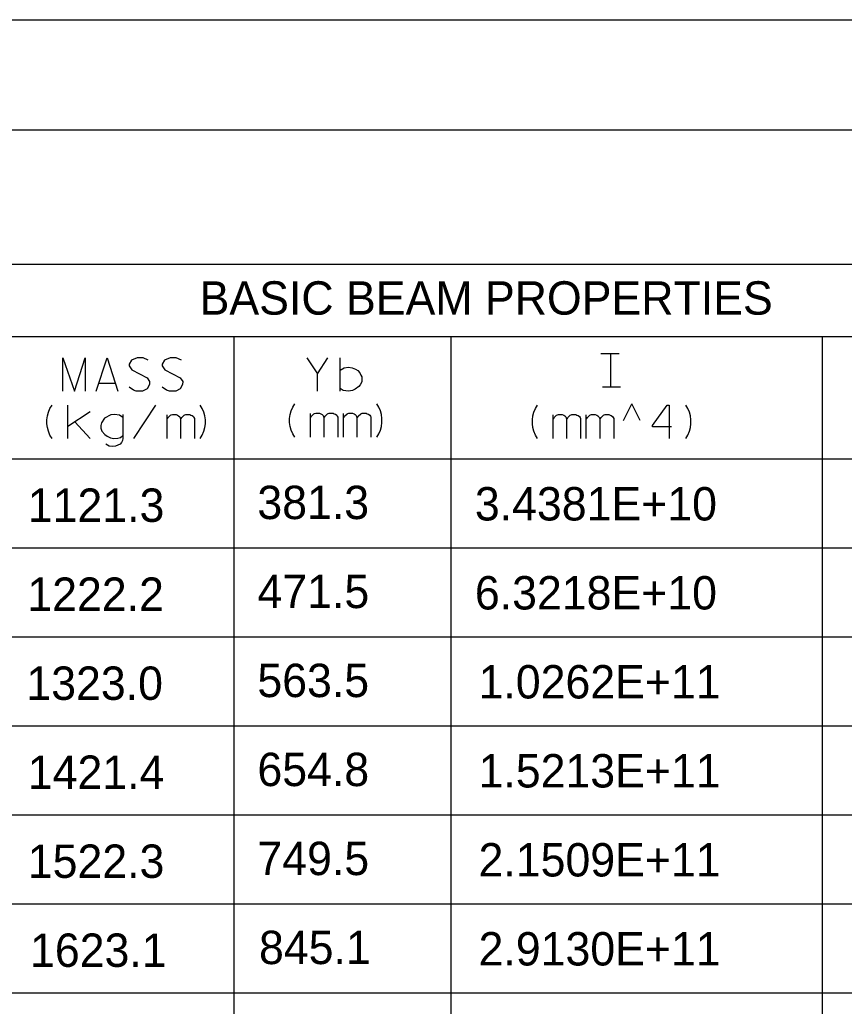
# Model space of a CAD drawing. Extents: x 635698 to 639877, y 296617 to 300175.
# Drawn here: x 637124.1 to 637198.2, y 298773.1 to 298861.8 of the extents above; entities that cross this region are included whole.
import ezdxf

# ---------------------------------------------------------------- set-up
doc = ezdxf.new("R2010")
doc.units = 0
doc.layers.add('2', color=7, linetype='Continuous')

msp = doc.modelspace()

# ---------------------------------------------------------------- linework, layer by layer
at = {"layer": '2'}
for p, q in [((636545.451, 298861.762), (637331.451, 298861.762)), ((637262.964, 298851.842), (636554.201, 298851.842)), ((637262.964, 298839.752), (636768.839, 298839.752)), ((637262.964, 298833.252), (637078.964, 298833.252)), ((637143.339, 298833.252), (637143.339, 298750.252)), ((637162.839, 298833.252), (637162.839, 298750.252)), ((637196.214, 298833.252), (637196.214, 298750.252)), ((637176.339, 298831.752), (637177.964, 298831.752)), ((637176.464, 298828.752), (637178.089, 298828.752)), ((637178.37, 298825.737), (637179.12, 298827.237)), ((637179.87, 298825.737), (637179.12, 298827.237)), ((637262.964, 298822.252), (636768.839, 298822.252)), ((637262.964, 298822.252), (637078.964, 298822.252)), ((637262.964, 298814.252), (636768.839, 298814.252)), ((637262.964, 298806.252), (636768.839, 298806.252)), ((637262.964, 298798.252), (636768.839, 298798.252)), ((637262.964, 298790.252), (636768.839, 298790.252)), ((637262.964, 298782.252), (636768.839, 298782.252)), ((637262.964, 298774.252), (636768.839, 298774.252))]:
    msp.add_line(p, q, dxfattribs=at)
for points in [[(637127.992, 298828.381), (637127.992, 298831.381), (637129.032, 298828.381), (637130, 298831.381), (637130, 298828.381)], [(637130.969, 298828.381), (637131.961, 298831.381), (637132.929, 298828.381)], [(637135.67, 298831.169), (637135.197, 298831.381), (637134.654, 298831.381), (637134.158, 298831.169), (637133.945, 298830.791), (637133.945, 298830.649), (637134.182, 298830.295), (637135.552, 298829.586), (637135.788, 298829.255), (637135.764, 298828.972), (637135.552, 298828.594), (637135.15, 298828.381), (637134.583, 298828.381), (637134.323, 298828.476), (637133.945, 298828.735)], [(637138.646, 298831.169), (637138.174, 298831.381), (637137.631, 298831.381), (637137.135, 298831.169), (637136.922, 298830.791), (637136.922, 298830.649), (637137.158, 298830.295), (637138.528, 298829.586), (637138.765, 298829.255), (637138.741, 298828.972), (637138.528, 298828.594), (637138.127, 298828.381), (637137.56, 298828.381), (637137.3, 298828.476), (637136.922, 298828.735)], [(637149.921, 298831.381), (637150.866, 298829.94), (637151.81, 298831.381)], [(637152.897, 298828.381), (637152.897, 298831.381)], [(637176.875, 298831.752), (637177.584, 298831.752)], [(637177.23, 298828.752), (637177.23, 298831.752)], [(637152.897, 298830.271), (637153.275, 298830.484), (637153.653, 298830.531), (637153.984, 298830.484), (637154.291, 298830.342), (637154.48, 298830.224), (637154.669, 298830.011), (637154.763, 298829.822), (637154.858, 298829.657), (637154.858, 298829.208), (637154.716, 298828.948), (637154.598, 298828.806), (637154.244, 298828.546), (637154.008, 298828.429), (637153.653, 298828.381), (637153.181, 298828.429), (637152.897, 298828.618)], [(637150.866, 298828.381), (637150.866, 298829.94)], [(637131.205, 298829.09), (637132.693, 298829.09)], [(637176.875, 298828.752), (637177.584, 298828.752)], [(637127.023, 298824.128), (637126.834, 298824.435), (637126.693, 298824.765), (637126.598, 298825.096), (637126.551, 298825.45), (637126.551, 298825.805), (637126.598, 298826.159), (637126.693, 298826.49), (637126.834, 298826.82), (637127.023, 298827.128)], [(637128.426, 298824.128), (637128.426, 298827.128)], [(637134.379, 298824.128), (637136.339, 298827.128)], [(637140.332, 298824.128), (637140.521, 298824.435), (637140.663, 298824.765), (637140.757, 298825.096), (637140.805, 298825.45), (637140.805, 298825.805), (637140.757, 298826.159), (637140.663, 298826.49), (637140.521, 298826.82), (637140.332, 298827.128)], [(637148.834, 298824.245), (637148.645, 298824.552), (637148.504, 298824.883), (637148.409, 298825.213), (637148.362, 298825.568), (637148.362, 298825.922), (637148.409, 298826.277), (637148.504, 298826.607), (637148.645, 298826.938), (637148.834, 298827.245)], [(637156.19, 298824.245), (637156.379, 298824.552), (637156.521, 298824.883), (637156.615, 298825.213), (637156.662, 298825.568), (637156.662, 298825.922), (637156.615, 298826.277), (637156.521, 298826.607), (637156.379, 298826.938), (637156.19, 298827.245)], [(637170.645, 298824.128), (637170.456, 298824.435), (637170.315, 298824.765), (637170.22, 298825.096), (637170.173, 298825.45), (637170.173, 298825.805), (637170.22, 298826.159), (637170.315, 298826.49), (637170.456, 298826.82), (637170.645, 298827.128)], [(637182.678, 298825.167), (637180.978, 298825.167), (637180.978, 298825.285), (637182.3, 298827.128), (637182.466, 298827.128), (637182.466, 298824.128)], [(637183.954, 298824.128), (637184.143, 298824.435), (637184.285, 298824.765), (637184.379, 298825.096), (637184.427, 298825.45), (637184.427, 298825.805), (637184.379, 298826.159), (637184.285, 298826.49), (637184.143, 298826.82), (637183.954, 298827.128)], [(637130.458, 298826.513), (637128.426, 298825.214)], [(637133.387, 298826.017), (637133.08, 298826.23), (637132.631, 298826.277), (637132.3, 298826.254), (637131.733, 298825.946), (637131.45, 298825.521), (637131.403, 298825.285), (637131.403, 298825.049), (637131.497, 298824.765), (637131.757, 298824.482), (637131.969, 298824.316), (637132.276, 298824.175), (637132.56, 298824.128), (637132.938, 298824.151), (637133.174, 298824.222), (637133.387, 298824.387)], [(637133.387, 298826.277), (637133.387, 298824.128), (637133.34, 298823.939), (637133.268, 298823.773), (637133.127, 298823.608), (637132.938, 298823.513), (637132.725, 298823.443), (637132.465, 298823.395), (637132.158, 298823.443), (637131.852, 298823.608)], [(637137.356, 298825.875), (637137.403, 298825.923), (637137.45, 298826.017), (637137.663, 298826.23), (637137.734, 298826.254), (637137.828, 298826.277), (637138.159, 298826.277), (637138.301, 298826.23), (637138.395, 298826.159), (637138.49, 298826.065), (637138.561, 298825.899), (637138.584, 298825.852), (637138.631, 298825.923), (637138.678, 298826.017), (637138.891, 298826.23), (637138.962, 298826.254), (637139.033, 298826.277), (637139.387, 298826.277), (637139.482, 298826.23), (637139.6, 298826.183), (637139.718, 298826.088), (637139.765, 298826.017), (637139.812, 298825.923), (637139.812, 298824.128)], [(637137.356, 298824.128), (637137.356, 298826.254)], [(637138.584, 298824.128), (637138.584, 298825.875)], [(637150.237, 298825.993), (637150.284, 298826.04), (637150.331, 298826.135), (637150.544, 298826.348), (637150.615, 298826.371), (637150.709, 298826.395), (637151.04, 298826.395), (637151.182, 298826.348), (637151.277, 298826.277), (637151.371, 298826.182), (637151.442, 298826.017), (637151.465, 298825.97), (637151.512, 298826.04), (637151.56, 298826.135), (637151.772, 298826.348), (637151.843, 298826.371), (637151.914, 298826.395), (637152.269, 298826.395), (637152.363, 298826.348), (637152.481, 298826.3), (637152.599, 298826.205), (637152.646, 298826.135), (637152.693, 298826.04), (637152.693, 298824.245)], [(637150.237, 298824.245), (637150.237, 298826.371)], [(637151.465, 298824.245), (637151.465, 298825.993)], [(637153.214, 298825.993), (637153.261, 298826.04), (637153.308, 298826.135), (637153.521, 298826.348), (637153.591, 298826.371), (637153.686, 298826.395), (637154.017, 298826.395), (637154.158, 298826.348), (637154.253, 298826.277), (637154.348, 298826.182), (637154.418, 298826.017), (637154.442, 298825.97), (637154.489, 298826.04), (637154.536, 298826.135), (637154.749, 298826.348), (637154.82, 298826.371), (637154.891, 298826.395), (637155.245, 298826.395), (637155.34, 298826.348), (637155.458, 298826.3), (637155.576, 298826.205), (637155.623, 298826.135), (637155.67, 298826.04), (637155.67, 298824.245)], [(637153.214, 298824.245), (637153.214, 298826.371)], [(637154.442, 298824.245), (637154.442, 298825.993)], [(637172.048, 298825.875), (637172.095, 298825.923), (637172.142, 298826.017), (637172.355, 298826.23), (637172.426, 298826.254), (637172.52, 298826.277), (637172.851, 298826.277), (637172.993, 298826.23), (637173.088, 298826.159), (637173.182, 298826.065), (637173.253, 298825.899), (637173.276, 298825.852), (637173.323, 298825.923), (637173.371, 298826.017), (637173.583, 298826.23), (637173.654, 298826.254), (637173.725, 298826.277), (637174.08, 298826.277), (637174.174, 298826.23), (637174.292, 298826.183), (637174.41, 298826.088), (637174.457, 298826.017), (637174.504, 298825.923), (637174.504, 298824.128)], [(637172.048, 298824.128), (637172.048, 298826.254)], [(637173.276, 298824.128), (637173.276, 298825.875)], [(637175.024, 298825.875), (637175.072, 298825.923), (637175.119, 298826.017), (637175.332, 298826.23), (637175.402, 298826.254), (637175.497, 298826.277), (637175.828, 298826.277), (637175.969, 298826.23), (637176.064, 298826.159), (637176.159, 298826.065), (637176.229, 298825.899), (637176.253, 298825.852), (637176.3, 298825.923), (637176.347, 298826.017), (637176.56, 298826.23), (637176.631, 298826.254), (637176.702, 298826.277), (637177.056, 298826.277), (637177.151, 298826.23), (637177.269, 298826.183), (637177.386, 298826.088), (637177.434, 298826.017), (637177.481, 298825.923), (637177.481, 298824.128)], [(637175.024, 298824.128), (637175.024, 298826.254)], [(637176.253, 298824.128), (637176.253, 298825.875)], [(637129.064, 298825.616), (637130.458, 298824.128)]]:
    msp.add_lwpolyline(points, dxfattribs=at)

# ---------------------------------------------------------------- texts
for s, p in [('BASIC BEAM PROPERTIES', (637140.277, 298835.252)), ('1121.3', (637124.842, 298816.627)), ('381.3', (637145.466, 298816.877)), ('3.4381E+10', (637165.011, 298816.752)), ('1222.2', (637124.8, 298808.627)), ('471.5', (637145.479, 298808.877)), ('6.3218E+10', (637165.011, 298808.752)), ('1323.0', (637124.713, 298800.627)), ('563.5', (637145.467, 298800.877)), ('1.0262E+11', (637165.342, 298800.752)), ('1421.4', (637124.843, 298792.627)), ('654.8', (637145.472, 298792.877)), ('1.5213E+11', (637165.341, 298792.752)), ('1522.3', (637124.842, 298784.627)), ('749.5', (637145.472, 298784.877)), ('2.1509E+11', (637165.341, 298784.752)), ('1623.1', (637125.042, 298776.627)), ('845.1', (637145.614, 298776.877)), ('2.9130E+11', (637165.343, 298776.752))]:
    msp.add_text(s, height=3, dxfattribs=at).set_placement(p)

doc.saveas('drawing.dxf')
